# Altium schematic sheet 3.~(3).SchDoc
size 420 x 297 mm
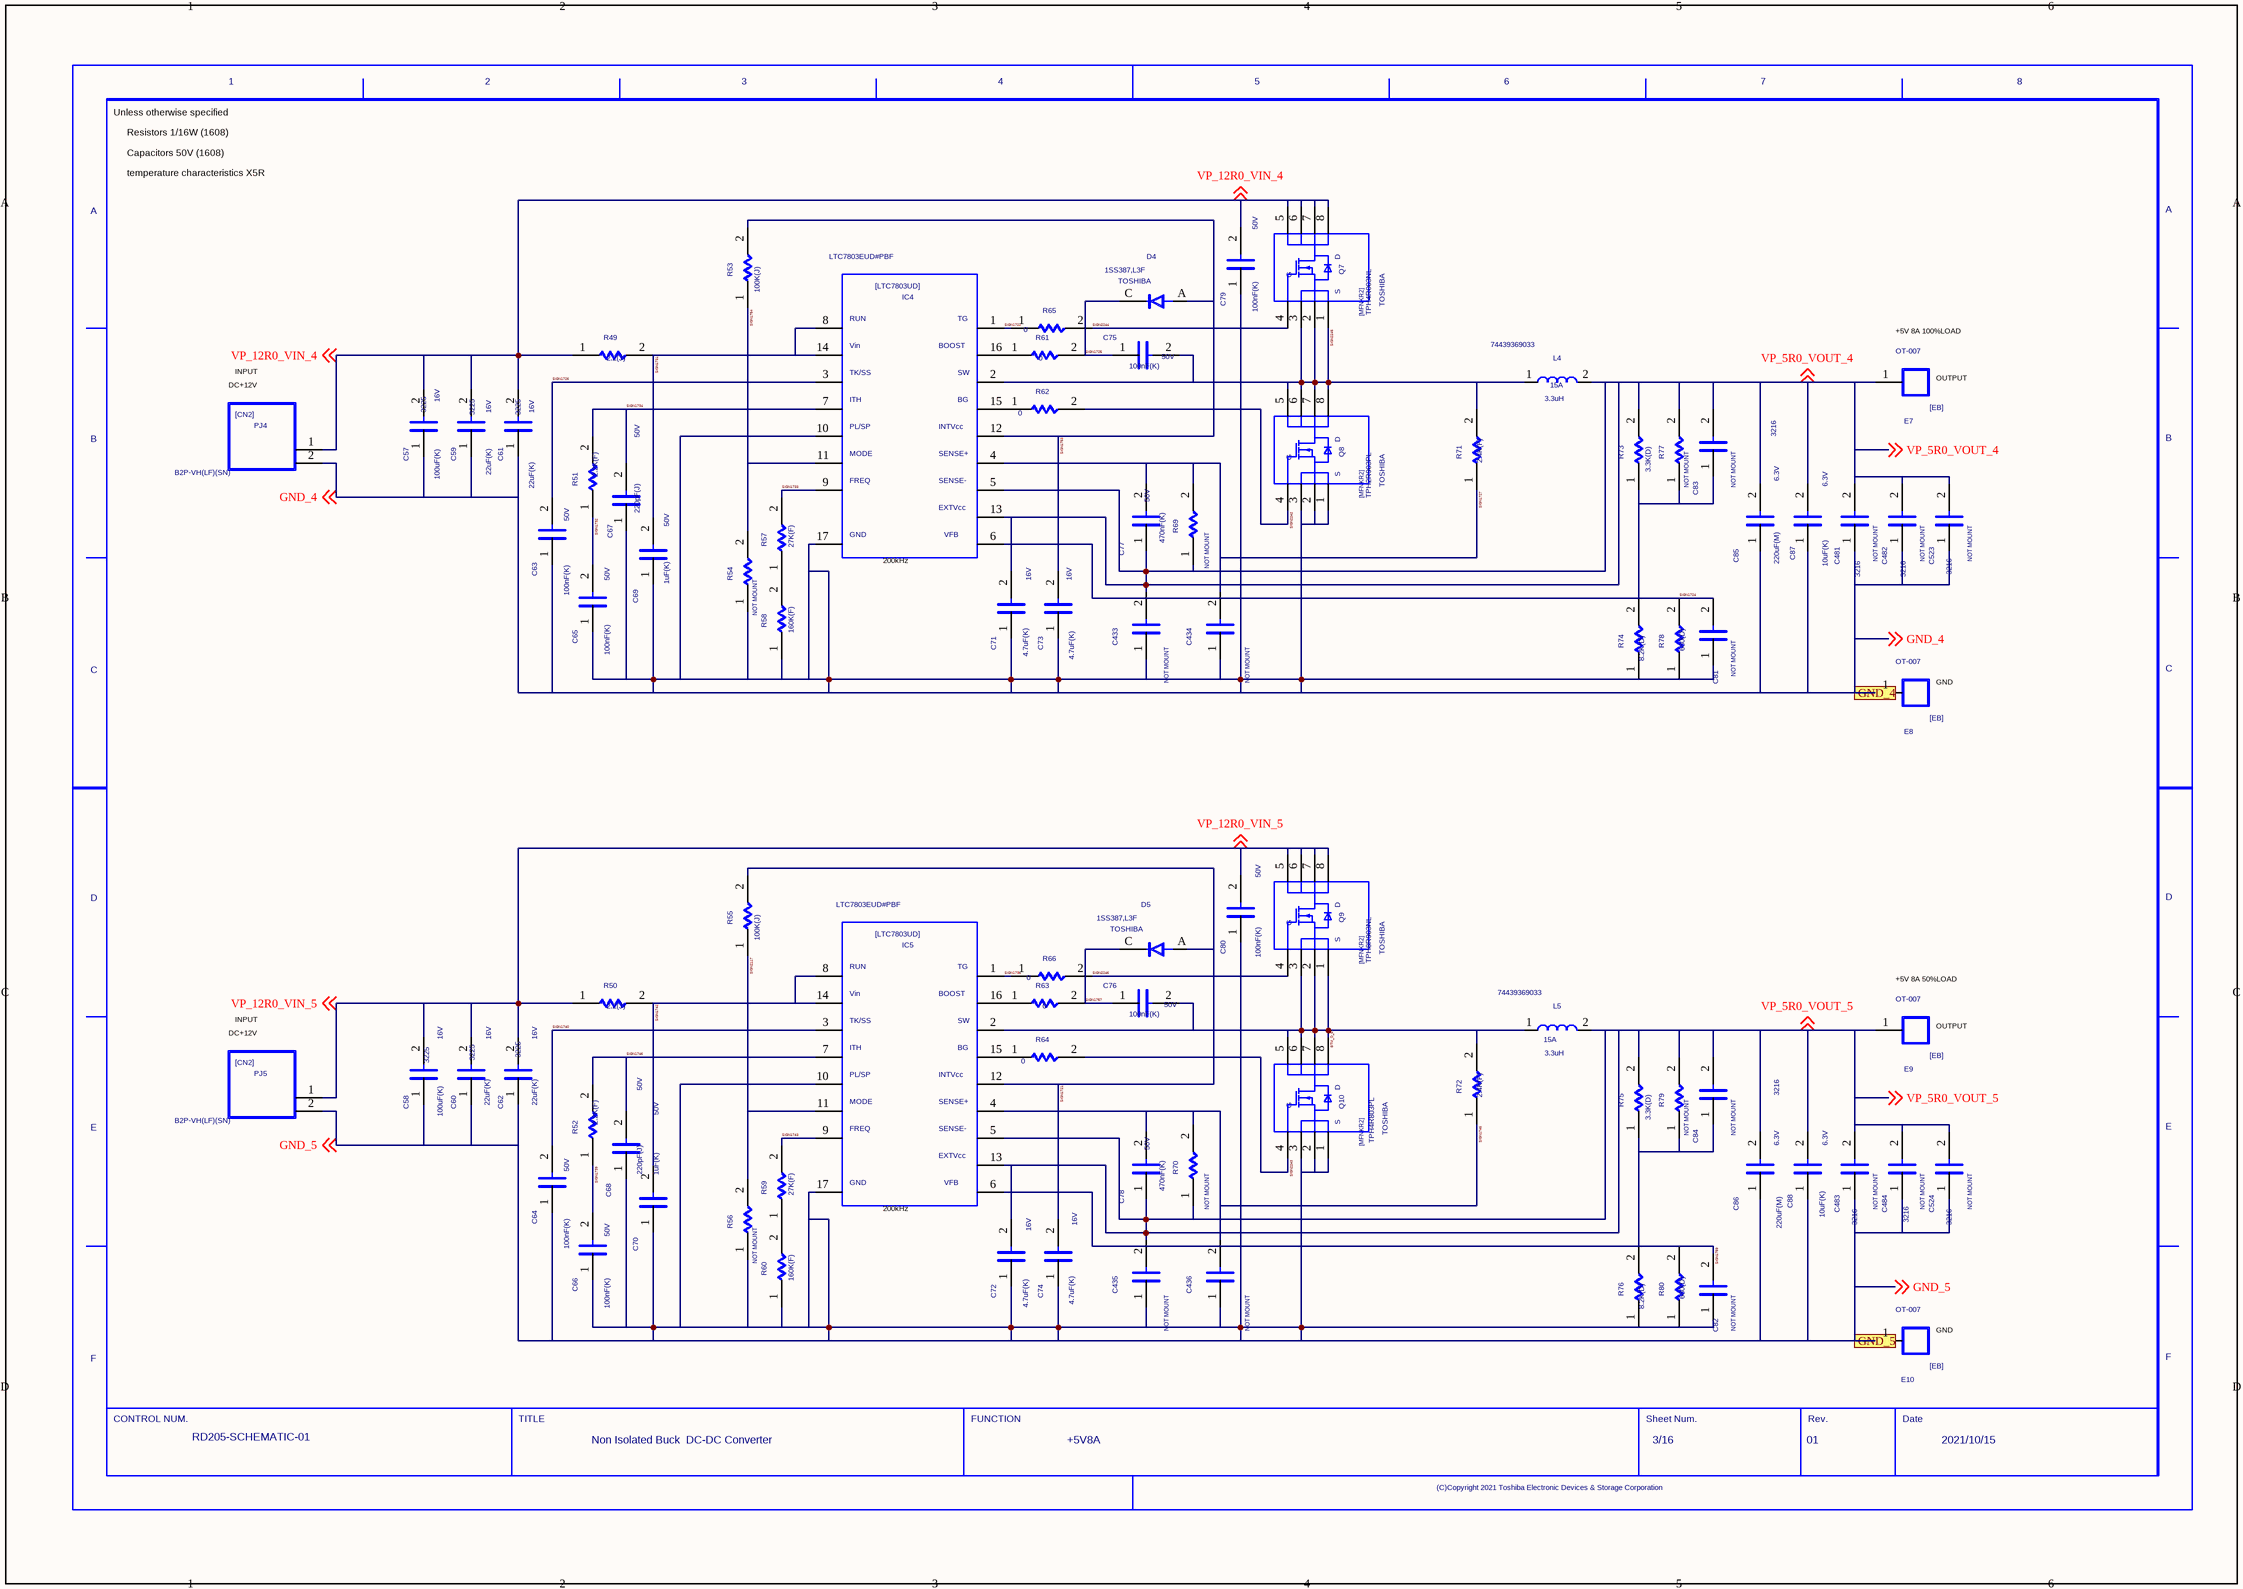
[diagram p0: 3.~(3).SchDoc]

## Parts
C57  SIZECODESMD: 3225  VAL2: 16V  VAL1: 100uF(K)  (hidden comment: C)
C58  SIZECODESMD: 3225  VAL2: 16V  VAL1: 100uF(K)  (hidden comment: C)
C59  SIZECODESMD: 3225  VAL2: 16V  VAL1: 22uF(K)  (hidden comment: C)
C60  SIZECODESMD: 3225  VAL2: 16V  VAL1: 22uF(K)  (hidden comment: C)
C61  SIZECODESMD: 3225  VAL2: 16V  VAL1: 22uF(K)  (hidden comment: C)
C62  SIZECODESMD: 3225  VAL2: 16V  VAL1: 22uF(K)  (hidden comment: C)
C63  VAL2: 50V  VAL1: 100nF(K)  (hidden comment: C)
C64  VAL2: 50V  VAL1: 100nF(K)  (hidden comment: C)
C65  VAL2: 50V  VAL1: 100nF(K)  (hidden comment: C)
C66  VAL2: 50V  VAL1: 100nF(K)  (hidden comment: C)
C67  VAL2: 50V  VAL1: 220pF(J)  (hidden comment: C)
C68  VAL2: 50V  VAL1: 220pF(J)  (hidden comment: C)
C69  VAL2: 50V  VAL1: 1uF(K)  (hidden comment: C)
C70  VAL2: 50V  VAL1: 1uF(K)  (hidden comment: C)
C71  VAL2: 16V  VAL1: 4.7uF(K)  (hidden comment: C)
C72  VAL2: 16V  VAL1: 4.7uF(K)  (hidden comment: C)
C73  VAL2: 16V  VAL1: 4.7uF(K)  (hidden comment: C)
C74  VAL2: 16V  VAL1: 4.7uF(K)  (hidden comment: C)
C75  VAL2: 50V  VAL1: 100nF(K)  (hidden comment: C)
C76  VAL2: 50V  VAL1: 100nF(K)  (hidden comment: C)
C77  VAL2: 50V  VAL1: 470nF(K)  (hidden comment: C)
C78  VAL2: 50V  VAL1: 470nF(K)  (hidden comment: C)
C79  VAL2: 50V  VAL1: 100nF(K)  (hidden comment: C)
C80  VAL2: 50V  VAL1: 100nF(K)  (hidden comment: C)
C81  NOTMOUNT: NOT MOUNT  (hidden comment: C)
C82  NOTMOUNT: NOT MOUNT  (hidden comment: C)
C83  NOTMOUNT: NOT MOUNT  (hidden comment: C)
C84  NOTMOUNT: NOT MOUNT  (hidden comment: C)
C85  SIZECODESMD: 3216  VAL2: 6.3V  VAL1: 220uF(M)  (hidden comment: C)
C86  SIZECODESMD: 3216  VAL2: 6.3V  VAL1: 220uF(M)  (hidden comment: C)
C87  VAL2: 6.3V  VAL1: 10uF(K)  (hidden comment: C)
C88  VAL2: 6.3V  VAL1: 10uF(K)  (hidden comment: C)
C433  NOTMOUNT: NOT MOUNT  (hidden comment: C)
C434  NOTMOUNT: NOT MOUNT  (hidden comment: C)
C435  NOTMOUNT: NOT MOUNT  (hidden comment: C)
C436  NOTMOUNT: NOT MOUNT  (hidden comment: C)
C481  NOTMOUNT: NOT MOUNT  SIZECODESMD: 3216  (hidden comment: C)
C482  NOTMOUNT: NOT MOUNT  SIZECODESMD: 3216  (hidden comment: C)
C483  NOTMOUNT: NOT MOUNT  SIZECODESMD: 3216  (hidden comment: C)
C484  NOTMOUNT: NOT MOUNT  SIZECODESMD: 3216  (hidden comment: C)
C523  NOTMOUNT: NOT MOUNT  SIZECODESMD: 3216  (hidden comment: C)
C524  NOTMOUNT: NOT MOUNT  SIZECODESMD: 3216  (hidden comment: C)
D4  USERCOMPTEXT3: TOSHIBA  VAL3: 1SS387,L3F  (hidden comment: D)
D5  USERCOMPTEXT3: TOSHIBA  VAL3: 1SS387,L3F  (hidden comment: D)
E7  VAL3: OT-007  (hidden comment: EB)
E8  VAL3: OT-007  (hidden comment: EB)
E9  VAL3: OT-007  (hidden comment: EB)
E10  VAL3: OT-007  (hidden comment: EB)
IC4  VAL3: LTC7803EUD#PBF  (hidden comment: LTC7803UD)
IC5  VAL3: LTC7803EUD#PBF  (hidden comment: LTC7803UD)
L4  VAL3: 74439369033  VAL2: 15A  VAL1: 3.3uH  (hidden comment: L)
L5  VAL3: 74439369033  VAL2: 15A  VAL1: 3.3uH  (hidden comment: L)
PJ4  VAL3: B2P-VH(LF)(SN)  (hidden comment: CN2)
PJ5  VAL3: B2P-VH(LF)(SN)  (hidden comment: CN2)
Q7  USERCOMPTEXT3: TOSHIBA  VAL3: TPH4R003NL  (hidden comment: MFNKR2)
Q8  USERCOMPTEXT3: TOSHIBA  VAL3: TPH2R903PL  (hidden comment: MFNKR2)
Q9  USERCOMPTEXT3: TOSHIBA  VAL3: TPH8R903NL  (hidden comment: MFNKR2)
Q10  USERCOMPTEXT3: TOSHIBA  VAL3: TPH4R803PL  (hidden comment: MFNKR2)
R49  VAL1: 2.2(J)  (hidden comment: R)
R50  VAL1: 2.2(J)  (hidden comment: R)
R51  VAL1: 2.2K(F)  (hidden comment: R)
R52  VAL1: 2.2K(F)  (hidden comment: R)
R53  VAL1: 100K(J)  (hidden comment: R)
R54  NOTMOUNT: NOT MOUNT  (hidden comment: R)
R55  VAL1: 100K(J)  (hidden comment: R)
R56  NOTMOUNT: NOT MOUNT  (hidden comment: R)
R57  VAL1: 27K(F)  (hidden comment: R)
R58  VAL1: 160K(F)  (hidden comment: R)
R59  VAL1: 27K(F)  (hidden comment: R)
R60  VAL1: 160K(F)  (hidden comment: R)
R61  VAL1: 0  (hidden comment: R)
R62  VAL1: 0  (hidden comment: R)
R63  VAL1: 0  (hidden comment: R)
R64  VAL1: 0  (hidden comment: R)
R65  VAL1: 0  (hidden comment: R)
R66  VAL1: 0  (hidden comment: R)
R69  NOTMOUNT: NOT MOUNT  (hidden comment: R)
R70  NOTMOUNT: NOT MOUNT  (hidden comment: R)
R71  VAL1: 2.4K(F)  (hidden comment: R)
R72  VAL1: 2.4K(F)  (hidden comment: R)
R73  VAL1: 3.3K(D)  (hidden comment: R)
R74  VAL1: 8.2K(D)  (hidden comment: R)
R75  VAL1: 3.3K(D)  (hidden comment: R)
R76  VAL1: 8.2K(D)  (hidden comment: R)
R77  NOTMOUNT: NOT MOUNT  (hidden comment: R)
R78  VAL1: 680(D)  (hidden comment: R)
R79  NOTMOUNT: NOT MOUNT  (hidden comment: R)
R80  VAL1: 680(D)  (hidden comment: R)
U?  DATE: 2021/10/15  SHEETNUMBER: 3/16  TITLE: Non Isolated Buck / DC-DC Converter  REVISION: 01  DRAWINGNUMBER: RD205-SCHEMATIC-01  FUNCTION: +5V8A  (hidden comment: WAKU_DEF100)

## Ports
GND_4, GND_5

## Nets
BTM_D_5: C76.2 IC5.2 L5.1 Q9.1 Q9.2 Q9.3 Q10.5 Q10.6 Q10.7 Q10.8 R72.2
GND_4: C57.1 C59.1 C61.1 C63.1 C65.1 C67.1 C69.1 C71.1 C73.1 C79.1 C81.1 C85.1 C87.1 C433.1 C434.1 C481.1 C482.1 C523.1 E8.1 IC4.10 IC4.17 PJ4.2 Q8.1 Q8.2 Q8.3 R54.1 R58.1 R74.1 R78.1 ; off-sheet GND_4, port GND_4
GND_5: C58.1 C60.1 C62.1 C64.1 C66.1 C68.1 C70.1 C72.1 C74.1 C80.1 C82.1 C86.1 C88.1 C435.1 C436.1 C483.1 C484.1 C524.1 E10.1 IC5.10 IC5.17 PJ5.2 Q10.1 Q10.2 Q10.3 R56.1 R60.1 R76.1 R80.1 ; off-sheet GND_5, port GND_5
SIGN1721: C74.2 D5.A IC5.12 R55.2
SIGN1722: IC4.1 R65.1
SIGN1724: C81.2 C83.1 IC4.6 R73.1 R74.2 R77.1 R78.2
SIGN1725: C75.1 D4.C R61.2
SIGN1726: C63.2 IC4.3
SIGN1727: C77.2 C434.2 IC4.4 R69.2 R71.1
SIGN1731: C69.2 IC4.8 IC4.14 R49.2
SIGN1732: C65.2 R51.1
SIGN1733: IC4.9 R57.2
SIGN1734: C67.2 IC4.7 R51.2
SIGN1736: IC5.1 R66.1
SIGN1739: C66.2 R52.1
SIGN1740: C64.2 IC5.3
SIGN1742: C70.2 IC5.8 IC5.14 R50.2
SIGN1743: IC5.9 R59.2
SIGN1745: C78.2 C436.2 IC5.4 R70.2 R72.1
SIGN1746: C68.2 IC5.7 R52.2
SIGN1753: C73.2 D4.A IC4.12 R53.2
SIGN1754: IC4.11 R53.1 R54.2
SIGN1757: C76.1 D5.C R63.2
SIGN1759: C82.2 C84.1 IC5.6 R75.1 R76.2 R79.1 R80.2
SIGN2117: IC5.11 R55.1 R56.2
SIGN2242: Q8.4 R62.2
SIGN2243: Q10.4 R64.2
SIGN2244: Q7.4 R65.2
SIGN2245: C75.2 IC4.2 L4.1 Q7.1 Q7.2 Q7.3 Q8.5 Q8.6 Q8.7 Q8.8 R71.2
SIGN2246: Q9.4 R66.2
VP_5R0_VOUT_4: C71.2 C77.1 C83.2 C85.2 C87.2 C433.2 C481.2 C482.2 C523.2 E7.1 IC4.5 IC4.13 L4.2 R69.1 R73.2 R77.2 ; off-sheet VP_5R0_VOUT_4
VP_5R0_VOUT_5: C72.2 C78.1 C84.2 C86.2 C88.2 C435.2 C483.2 C484.2 C524.2 E9.1 IC5.5 IC5.13 L5.2 R70.1 R75.2 R79.2 ; off-sheet VP_5R0_VOUT_5
VP_12R0_VIN_4: C57.2 C59.2 C61.2 C79.2 PJ4.1 Q7.5 Q7.6 Q7.7 Q7.8 R49.1 ; off-sheet VP_12R0_VIN_4
VP_12R0_VIN_5: C58.2 C60.2 C62.2 C80.2 PJ5.1 Q9.5 Q9.6 Q9.7 Q9.8 R50.1 ; off-sheet VP_12R0_VIN_5
NetIC4_15: IC4.15 R62.1
NetIC4_16: IC4.16 R61.1
NetIC5_15: IC5.15 R64.1
NetIC5_16: IC5.16 R63.1
NetR57_1: R57.1 R58.2
NetR59_1: R59.1 R60.2

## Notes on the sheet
- Unless otherwise specified
- Resistors 1/16W (1608)
- Capacitors 50V (1608)
- temperature characteristics X5R
- DC+12V
- INPUT
- (near E7) +5V 8A 100%LOAD
- (near E7) OUTPUT
- (near IC4) 200kHz
- (near E8) GND
- (near E9) +5V 8A 50%LOAD
- (near E9) OUTPUT
- (near IC5) 200kHz
- (near E10) GND

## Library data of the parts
C57 C58 = C_Dup1: SQ_PART_MODEL: CON_100n; FNPARTSNAMEG: CHIP CERAMIC CAPACITOR (3225); USEINPARTSLIST: YES; OriginalSymbolOrigin: (2540,7620); MFSOLDERINGPROP: .; TEMPCHARACTERI2: B; MFFORMINGDIVP: KC; OUMECLASSIFICATION: セラミックコンデンサ; MFMOUNTSYMBOLP: 90; CDMASTERCADCELG: DC903A; PCODE: P03276001115; FNCLASSCODEG: P03-03; MAXGCOUNT: 1; RATEDVOLTAGE: 250; COMPONENTNAME: G36030160049; OUMEMAKER: KYC 京セラ; MFPACKAGEMETHOP: S; NOMINALCAPACITA: 100n; OUMEMAKERKATAMEI: CF32W5R104K250AT; CAPACITANCETOLE: K
C59-C62 = C_Dup1: SQ_PART_MODEL: CON_22u; FNPARTSNAMEG: CHIP CERAMIC CAPACITOR (3225); USEINPARTSLIST: YES; OriginalSymbolOrigin: (2540,7620); MFSOLDERINGPROP: .; TEMPCHARACTERI2: B; MFFORMINGDIVP: KC; OUMECLASSIFICATION: セラミックコンデンサ; MFMOUNTSYMBOLP: 80; CDMASTERCADCELG: DC903A; PCODE: P03043035626; FNCLASSCODEG: P03-03; MAXGCOUNT: 1; RATEDVOLTAGE: 6.3; COMPONENTNAME: G36030119054; OUMEMAKER: TYD 太陽誘電; MFPACKAGEMETHOP: S; NOMINALCAPACITA: 22u; OUMEMAKERKATAMEI: JMK325BJ226KM-T; CAPACITANCETOLE: K
C63-C66 C75 C76 C79 C80 = C_Dup1: SQ_PART_MODEL: CON_100n; FNPARTSNAMEG: CHIP CERAMIC CAPACITOR (1608); USEINPARTSLIST: YES; OriginalSymbolOrigin: (2540,7620); MFSOLDERINGPROP: .; TEMPCHARACTERI2: B; MFFORMINGDIVP: KC; OUMECLASSIFICATION: セラミックコンデンサ; SIZECODESMD: 1608; MFMOUNTSYMBOLP: 80; CDMASTERCADCELG: C8100E; PCODE: P03B000000E4; FNCLASSCODEG: P03-03; MAXGCOUNT: 1; RATEDVOLTAGE: 16; COMPONENTNAME: GDM030000598; OUMEMAKER: MRT 村田製作所; MFPACKAGEMETHOP: S; NOMINALCAPACITA: 100n; OUMEMAKERKATAMEI: GRM188B11C104KA01C; CAPACITANCETOLE: K
C67 C68 = C_Dup1: SQ_PART_MODEL: CON_220p; FNPARTSNAMEG: CHIP CERAMIC CAPACITOR (1608); USEINPARTSLIST: YES; OriginalSymbolOrigin: (2540,7620); CDMASTERCADCELG: C8100E; MFSOLDERINGPROP: .; TEMPCHARACTERI2: CH; MFFORMINGDIVP: KC; OUMECLASSIFICATION: セラミックコンデンサ; SIZECODESMD: 1608; MFMOUNTSYMBOLP: 80; PCODE: P03039269127; FNCLASSCODEG: P03-03; MAXGCOUNT: 1; RATEDVOLTAGE: 50; COMPONENTNAME: G36030011488; OUMEMAKER: KYC 京セラ; MFPACKAGEMETHOP: S; NOMINALCAPACITA: 220p; OUMEMAKERKATAMEI: CM105CH221J50AT; CAPACITANCETOLE: J
C69 C70 = C_Dup1: SQ_PART_MODEL: CON_1u; FNPARTSNAMEG: CHIP CERAMIC CAPACITOR (1608); USEINPARTSLIST: YES; OriginalSymbolOrigin: (2540,7620); MFSOLDERINGPROP: .; TEMPCHARACTERI2: B; MFFORMINGDIVP: KC; OUMECLASSIFICATION: セラミックコンデンサ; SIZECODESMD: 1608; MFMOUNTSYMBOLP: 80; CDMASTERCADCELG: C8100E; PCODE: P03039ACE122; FNCLASSCODEG: P03-03; MAXGCOUNT: 1; RATEDVOLTAGE: 6.3; COMPONENTNAME: G36030104159; OUMEMAKER: KYC 京セラ; MFPACKAGEMETHOP: S; NOMINALCAPACITA: 1u; OUMEMAKERKATAMEI: CM105B105K06ATN; CAPACITANCETOLE: K
C71 C72 = C_Dup1: SQ_PART_MODEL: CON_4.7u; FNPARTSNAMEG: CHIP CERAMIC CAPACITOR (1608); USEINPARTSLIST: YES; OriginalSymbolOrigin: (2540,7620); PCODE: P03B000000MS; MFSOLDERINGPROP: .; TEMPCHARACTERI2: B; MFFORMINGDIVP: KC; OUMECLASSIFICATION: セラミックコンデンサ; SIZECODESMD: 1608; MFMOUNTSYMBOLP: 80; CDMASTERCADCELG: C8100E; FNCLASSCODEG: P03-03; MAXGCOUNT: 1; RATEDVOLTAGE: 4; COMPONENTNAME: GDM030000053; OUMEMAKER: KYC 京セラ; MFPACKAGEMETHOP: S; NOMINALCAPACITA: 4.7u; OUMEMAKERKATAMEI: CM105B475M04AT; CAPACITANCETOLE: M
C73 C74 = C_Dup1: SQ_PART_MODEL: CON_4.7u; FNPARTSNAMEG: CHIP CERAMIC CAPACITOR (1608); USEINPARTSLIST: YES; OriginalSymbolOrigin: (2540,7620); MFSOLDERINGPROP: .; TEMPCHARACTERI2: B; MFFORMINGDIVP: KC; OUMECLASSIFICATION: セラミックコンデンサ; SIZECODESMD: 1608; MFMOUNTSYMBOLP: 80; CDMASTERCADCELG: C8100E; PCODE: P03B000000MS; FNCLASSCODEG: P03-03; MAXGCOUNT: 1; RATEDVOLTAGE: 4; COMPONENTNAME: GDM030000053; OUMEMAKER: KYC 京セラ; MFPACKAGEMETHOP: S; NOMINALCAPACITA: 4.7u; OUMEMAKERKATAMEI: CM105B475M04AT; CAPACITANCETOLE: M
C77 C78 = C_Dup1: SQ_PART_MODEL: CON_470n; FNPARTSNAMEG: CHIP CERAMIC CAPACITOR (1608); USEINPARTSLIST: YES; OriginalSymbolOrigin: (2540,7620); MFSOLDERINGPROP: .; TEMPCHARACTERI2: B; MFFORMINGDIVP: KC; OUMECLASSIFICATION: セラミックコンデンサ; SIZECODESMD: 1608; MFMOUNTSYMBOLP: 80; CDMASTERCADCELG: C8100E; PCODE: P03039ABG127; FNCLASSCODEG: P03-03; MAXGCOUNT: 1; RATEDVOLTAGE: 10; COMPONENTNAME: GDM030001129; OUMEMAKER: KYC 京セラ; MFPACKAGEMETHOP: S; NOMINALCAPACITA: 470n; OUMEMAKERKATAMEI: CM105B474K10AT; CAPACITANCETOLE: K
C81-C84 = C_Dup1: SQ_PART_MODEL: CON_100p; FNPARTSNAMEG: CHIP CERAMIC CAPACITOR (1608); USEINPARTSLIST: YES; OriginalSymbolOrigin: (2540,7620); TOLERANCE: J; ASIMVALUE: 100P; MFSOLDERINGPROP: .; TEMPCHARACTERI2: CH; MFFORMINGDIVP: KC; OUMECLASSIFICATION: セラミックコンデンサ; SIZECODESMD: 1608; MFMOUNTSYMBOLP: 80; CDMASTERCADCELG: C8100E; PCODE: P03039177125; FNCLASSCODEG: P03-03; MAXGCOUNT: 1; RATEDVOLTAGE: 50; COMPONENTNAME: G36030011365; OUMEMAKER: KYC 京セラ; MFPACKAGEMETHOP: S; OUMEMAKERKATAMEI: CM105CH101J50AT; VAL2: 50V; VAL1: 100pF(J)
C85 C86 = C_Dup1: SQ_PART_MODEL: CON_22u; FNPARTSNAMEG: CHIP CERAMIC CAPACITOR (3216); USEINPARTSLIST: YES; OriginalSymbolOrigin: (2540,7620); MFSOLDERINGPROP: .; TEMPCHARACTERI2: B; MFFORMINGDIVP: KC; OUMECLASSIFICATION: セラミックコンデンサ; MFMOUNTSYMBOLP: 80; CDMASTERCADCELG: DC901A; PCODE: P03B0000004V; FNCLASSCODEG: P03-03; MAXGCOUNT: 1; RATEDVOLTAGE: 6.3; COMPONENTNAME: GDM030000020; OUMEMAKER: KYC 京セラ; MFPACKAGEMETHOP: S; NOMINALCAPACITA: 22u; OUMEMAKERKATAMEI: CM316B226M06AT; CAPACITANCETOLE: M
C87 C88 = C_Dup1: SQ_PART_MODEL: CON_1u; FNPARTSNAMEG: CHIP CERAMIC CAPACITOR (1608); PARTCOMMENT: 代表セル<KC0008> がフットプリントに登録されていません。; USEINPARTSLIST: YES; OriginalSymbolOrigin: (2540,7620); MFSOLDERINGPROP: .; TEMPCHARACTERI2: B; MFFORMINGDIVP: KC; OUMECLASSIFICATION: セラミックコンデンサ; SIZECODESMD: 1608; MFMOUNTSYMBOLP: 80; CDMASTERCADCELG: KC0008; PCODE: P03B000000ZQ; FNCLASSCODEG: P03-03; MAXGCOUNT: 1; RATEDVOLTAGE: 6.3; COMPONENTNAME: GDM030000202; OUMEMAKER: MRT 村田製作所; MFPACKAGEMETHOP: S; NOMINALCAPACITA: 1u; OUMEMAKERKATAMEI: GRM185B10J105KE21D; CAPACITANCETOLE: K
C433-C436 = C_Dup1: SQ_PART_MODEL: CON_220n; FNPARTSNAMEG: CHIP CERAMIC CAPACITOR (1608); PARTCOMMENT: 代表セル<KC0008> がフットプリントに登録されていません。; USEINPARTSLIST: YES; OriginalSymbolOrigin: (2540,7620); MFSOLDERINGPROP: .; TEMPCHARACTERI2: B; MFFORMINGDIVP: KC; OUMECLASSIFICATION: セラミックコンデンサ; SIZECODESMD: 1608; MFMOUNTSYMBOLP: 80; CDMASTERCADCELG: KC0008; PCODE: P03B000001L3; FNCLASSCODEG: P03-03; MAXGCOUNT: 1; RATEDVOLTAGE: 16; COMPONENTNAME: GDM030001129; OUMEMAKER: MRT 村田製作所; MFPACKAGEMETHOP: S; NOMINALCAPACITA: 220n; OUMEMAKERKATAMEI: GRM188B11C224KA01D; VAL2: 16V; VAL1: 220nF(K); CAPACITANCETOLE: K
C481-C484 C523 C524 = C_Dup1: SQ_PART_MODEL: CON_22u; FNPARTSNAMEG: CHIP CERAMIC CAPACITOR (3216); USEINPARTSLIST: YES; OriginalSymbolOrigin: (2540,7620); MFSOLDERINGPROP: .; TEMPCHARACTERI2: B; MFFORMINGDIVP: KC; OUMECLASSIFICATION: セラミックコンデンサ; MFMOUNTSYMBOLP: 80; CDMASTERCADCELG: DC901A; PCODE: P03B0000004V; FNCLASSCODEG: P03-03; MAXGCOUNT: 1; RATEDVOLTAGE: 6.3; COMPONENTNAME: GDM030000020; OUMEMAKER: KYC 京セラ; MFPACKAGEMETHOP: S; NOMINALCAPACITA: 22u; OUMEMAKERKATAMEI: CM316B226M06AT; VAL2: 6.3V; VAL1: 22uF(M); CAPACITANCETOLE: M
D4 D5 = D_Dup1: FNPARTSNAMEG: DIODE; USEINPARTSLIST: YES; PARTNAME: GDM420000143; SAVEAREA0: -565,-171,12979,8058; SAVECOUNT: 1; OriginalSymbolOrigin: (2540,5080); FORWARDVOLTAGEM: 0; MAXREVERSEVOLTA: 80; COMPONENTNAME: GDM420000143_package; MFSOLDERINGPROP: .; OUMEMAKER: TSB 東芝（ＹＰＳＳ）; QUADMODEL: dummymodel; MFPACKAGEMETHOP: S; MFFORMINGDIVP: MM; MOUNTINGFORMSMD: SMD; OUMECLASSIFICATION: 小信号ダイオード; OUMEMAKERKATAMEI: 1SS387(TPH3,F); CDMASTERCADCELG: D8101D; PCODE: P42B0000008E; FNCLASSCODEG: P42-01
E7-E10 = EB_Dup1: FNPARTSNAMEG: TERMINAL; USEINPARTSLIST: YES; PARTNAME: 5P9L1232P001; OUMEPARTTYPE: TB; OriginalSymbolOrigin: (2540,12700); COMPONENTNAME: 5P9L1232P001_package; MAXGCOUNT: 1; MFSOLDERINGPROP: .; OUMEMAKER: オサダ; QUADMODEL: dummymodel; MFPACKAGEMETHOP: I; MFFORMINGDIVP: OD; OUMECLASSIFICATION: 端子台、端子板; CDMASTERCADCELG: DE0009; KIND: PBS; PCODE: P29045001117; TERMINALSTYLE: SC; FNCLASSCODEG: P29-01
IC4 IC5 = LTC7803UD: USEINPARTSLIST: YES; SAVECOUNT: 29; SAVEAREA0: -53177,0,89020,58420; TIME: 16:14:14; UPDATEUSER: q91866sr; UPDATETIME: 13:15:36; OriginalSymbolOrigin: (5080,55880); MAXGCOUNT: 1; COMPONENTNAME: LTC7803UD_LTC7803UD; OUMEMAKER: ANALOG DEVICES
L4 L5 = L_Dup1: USEINPARTSLIST: YES; OriginalSymbolOrigin: (2540,5080); MAXGCOUNT: 1; COMPONENTNAME: L_L; OUMEMAKER: WURTH
PJ4 PJ5 = CN2_Dup1: FNPARTSNAMEG: 3.96PITCH NYLON CONNECTOR; USEINPARTSLIST: YES; PARTNAME: G36220114012; OUMEPARTTYPE: CN; OriginalSymbolOrigin: (2540,15240); MAXGCOUNT: 1; RATEDCURRENT: 7; COMPONENTNAME: G36220114012_package; MFSOLDERINGPROP: .; OUMEMAKER: JST 日本圧着端子製造; NUMBEROFCONTACT: 2; QUADMODEL: dummymodel; MFPACKAGEMETHOP: I; MFFORMINGDIVP: CU; CONTACTPITCH: 3.96m; OUMEMAKERKATAMEI: B2P-VH; CDMASTERCADCELG: DPJ514; PCODE: P22346001114; TERMINALSTYLE: PW; FNCLASSCODEG: P22-10
Q7-Q10 = MFNKR2: USEINPARTSLIST: YES; PARTNAME: TPH6R003NL; SAVEAREA0: -9199,-39,32138,22820; TIME: 18:57:44; UPDATEUSER: q91866sr; UPDATETIME: 12:36:02; SAVECOUNT: 10; OriginalSymbolOrigin: (5080,20320); MAXGCOUNT: 1; COMPONENTNAME: MFNKR2_MFNKR2
R49 R50 = R_Dup1: SQ_PART_MODEL: RES_2.2; FNPARTSNAMEG: CHIP RESISTOR (1608); USEINPARTSLIST: YES; OriginalSymbolOrigin: (5080,5080); TOLERANCE: J; ASIMVALUE: 2.2; MAXGCOUNT: 1; COMPONENTNAME: G36010011507; MFSOLDERINGPROP: .; OUMEMAKER: NAE 松下電子部品; MFPACKAGEMETHOP: S; MFFORMINGDIVP: KC; MOUNTINGFORMSMD: SMD; OUMECLASSIFICATION: 表面実装用固定抵抗器; MFMOUNTSYMBOLP: 80; POWERRATING: 63m; OUMEMAKERKATAMEI: ERJ3GEYJ2R2V; NUMBEROFELEMENT: 0; VAL2: 62.5mW; CDMASTERCADCELG: DR802R; PCODE: P01042157622; FNCLASSCODEG: P01-08
R51 R52 = R_Dup1: SQ_PART_MODEL: RES_2.2K; FNPARTSNAMEG: CHIP RESISTOR (1608); USEINPARTSLIST: YES; OriginalSymbolOrigin: (5080,5080); MAXGCOUNT: 1; COMPONENTNAME: G36010104339; MFSOLDERINGPROP: .; OUMEMAKER: KOA ＫＯＡ; MFPACKAGEMETHOP: S; MFFORMINGDIVP: KC; MOUNTINGFORMSMD: SMD; OUMECLASSIFICATION: 表面実装用固定抵抗器; RESISTANCETOLER: F; MFMOUNTSYMBOLP: 80; POWERRATING: 63m; OUMEMAKERKATAMEI: RK73H1JTD2201F; NOMINALRESISTAN: 2.2K; NUMBEROFELEMENT: 0; VAL2: 62.5mW; CDMASTERCADCELG: DR802R; PCODE: P01042159428; FNCLASSCODEG: P01-08
R53 R55 = R_Dup1: SQ_PART_MODEL: RES_100K; FNPARTSNAMEG: CHIP RESISTOR (1608); USEINPARTSLIST: YES; OriginalSymbolOrigin: (5080,5080); TOLERANCE: J; ASIMVALUE: 100K; MFSOLDERINGPROP: .; MFPACKAGEMETHOP: S; MFFORMINGDIVP: KC; MOUNTINGFORMSMD: SMD; MFMOUNTSYMBOLP: 80; NUMBEROFELEMENT: 0; PCODE: P01042047220; MAXGCOUNT: 1; COMPONENTNAME: G36010011057; OUMEMAKER: HDK 北陸電気工業; OUMECLASSIFICATION: 表面実装用固定抵抗器; POWERRATING: 63m; OUMEMAKERKATAMEI: CR1/16 104JV; VAL2: 62.5mW; CDMASTERCADCELG: DR802R; FNCLASSCODEG: P01-08
R54 R56 = R_Dup1: SQ_PART_MODEL: RES_10; FNPARTSNAMEG: CHIP RESISTOR (1608); USEINPARTSLIST: YES; OriginalSymbolOrigin: (5080,5080); TOLERANCE: F; ASIMVALUE: 10; MFSOLDERINGPROP: .; MFPACKAGEMETHOP: S; MFFORMINGDIVP: KC; MOUNTINGFORMSMD: SMD; MFMOUNTSYMBOLP: 80; NUMBEROFELEMENT: 0; PCODE: P01042036620; MAXGCOUNT: 1; COMPONENTNAME: G36010104063; OUMEMAKER: NAE 松下電子部品; OUMECLASSIFICATION: 表面実装用固定抵抗器; POWERRATING: 63m; OUMEMAKERKATAMEI: ERJ3GEYF100V; VAL2: 62.5mW; VAL1: 10(F); CDMASTERCADCELG: DR802R; FNCLASSCODEG: P01-08
R57 R59 = R_Dup1: SQ_PART_MODEL: RES_27K; FNPARTSNAMEG: CHIP RESISTOR (1608); USEINPARTSLIST: YES; OriginalSymbolOrigin: (5080,5080); MAXGCOUNT: 1; TOLERANCE: F; COMPONENTNAME: G36010027195; MFSOLDERINGPROP: .; OUMEMAKER: NAE 松下電子部品; MFPACKAGEMETHOP: S; MFFORMINGDIVP: KC; MOUNTINGFORMSMD: SMD; OUMECLASSIFICATION: 表面実装用固定抵抗器; ASIMVALUE: 27K; MFMOUNTSYMBOLP: 80; POWERRATING: 63m; OUMEMAKERKATAMEI: ERJ3GEYF273V; NUMBEROFELEMENT: 0; VAL2: 62.5mW; CDMASTERCADCELG: DR802R; PCODE: P01042508622; FNCLASSCODEG: P01-08
R58 R60 = R_Dup1: SQ_PART_MODEL: RES_160K; FNPARTSNAMEG: CHIP RESISTOR (1608); USEINPARTSLIST: YES; OriginalSymbolOrigin: (5080,5080); MAXGCOUNT: 1; COMPONENTNAME: G51011061108; MFSOLDERINGPROP: .; OUMEMAKER: HDK 北陸電気工業; MFPACKAGEMETHOP: S; MFFORMINGDIVP: KC; MOUNTINGFORMSMD: SMD; OUMECLASSIFICATION: 表面実装用固定抵抗器; RESISTANCETOLER: F; MFMOUNTSYMBOLP: 80; POWERRATING: 63m; OUMEMAKERKATAMEI: CR1/16 164FV; NOMINALRESISTAN: 160K; NUMBEROFELEMENT: 0; VAL2: 62.5mW; CDMASTERCADCELG: DR802R; PCODE: P01042125225; FNCLASSCODEG: P01-08
R61 R63 = R_Dup1: SQ_PART_MODEL: RES_10; FNPARTSNAMEG: CHIP RESISTOR (1608); USEINPARTSLIST: YES; OriginalSymbolOrigin: (5080,5080); TOLERANCE: F; ASIMVALUE: 10; MFSOLDERINGPROP: .; MFPACKAGEMETHOP: S; MFFORMINGDIVP: KC; MOUNTINGFORMSMD: SMD; MFMOUNTSYMBOLP: 80; PCODE: P01042036620; MAXGCOUNT: 1; COMPONENTNAME: G36010104063; OUMEMAKER: NAE 松下電子部品; OUMECLASSIFICATION: 表面実装用固定抵抗器; POWERRATING: 63m; OUMEMAKERKATAMEI: ERJ3GEYF100V; VAL2: 62.5mW; CDMASTERCADCELG: DR802R; FNCLASSCODEG: P01-08
R62 R64-R66 = R_Dup1: SQ_PART_MODEL: RES_10; FNPARTSNAMEG: CHIP RESISTOR (2012); USEINPARTSLIST: YES; OriginalSymbolOrigin: (5080,5080); MAXGCOUNT: 1; TOLERANCE: F; COMPONENTNAME: 5P9L1083P100; MFSOLDERINGPROP: .; OUMEMAKER: 北陸電気工業; MFPACKAGEMETHOP: S; MFFORMINGDIVP: KC; MOUNTINGFORMSMD: SMD; OUMECLASSIFICATION: 表面実装用固定抵抗器; ASIMVALUE: 10; MFMOUNTSYMBOLP: 90; POWERRATING: 100m; OUMEMAKERKATAMEI: CR1/10 100FV Pb(F); VAL2: 125mW; CDMASTERCADCELG: DR910A; PCODE: P01043091222; FNCLASSCODEG: P01-08
R69 R70 = R_Dup1: SQ_PART_MODEL: RES_47K; FNPARTSNAMEG: CHIP RESISTOR (1608); USEINPARTSLIST: YES; OriginalSymbolOrigin: (5080,5080); TOLERANCE: F; ASIMVALUE: 47K; MAXGCOUNT: 1; COMPONENTNAME: G36010027102; MFSOLDERINGPROP: .; OUMEMAKER: KOA ＫＯＡ; MFPACKAGEMETHOP: S; MFFORMINGDIVP: KC; MOUNTINGFORMSMD: SMD; OUMECLASSIFICATION: 表面実装用固定抵抗器; MFMOUNTSYMBOLP: 80; POWERRATING: 63m; OUMEMAKERKATAMEI: RK73H1JTD4702F; NUMBEROFELEMENT: 0; VAL2: 62.5mW; VAL1: 47K(F); CDMASTERCADCELG: DR802R; PCODE: P01042373428; FNCLASSCODEG: P01-08
R71 R72 = R_Dup1: SQ_PART_MODEL: RES_2.4K; FNPARTSNAMEG: CHIP RESISTOR (1608); USEINPARTSLIST: YES; OriginalSymbolOrigin: (5080,5080); TOLERANCE: F; ASIMVALUE: 2.4K; PCODE: P01042166327; MAXGCOUNT: 1; COMPONENTNAME: K0100562; MFSOLDERINGPROP: .; OUMEMAKER: KAM 釜屋電機; MFPACKAGEMETHOP: S; MFFORMINGDIVP: KC; MOUNTINGFORMSMD: SMD; OUMECLASSIFICATION: 表面実装用固定抵抗器; MFMOUNTSYMBOLP: 80; POWERRATING: 63m; OUMEMAKERKATAMEI: RMC1/16-242FTP; NUMBEROFELEMENT: 0; VAL2: 62.5mW; CDMASTERCADCELG: DR802R; FNCLASSCODEG: P01-08
R73 R75 = R_Dup1: SQ_PART_MODEL: RES_3.3K; FNPARTSNAMEG: CHIP RESISTOR (1608); USEINPARTSLIST: YES; OriginalSymbolOrigin: (5080,5080); MAXGCOUNT: 1; COMPONENTNAME: G36010014485; MFSOLDERINGPROP: .; OUMEMAKER: SSM 進工業; MFPACKAGEMETHOP: S; MFFORMINGDIVP: KC; MOUNTINGFORMSMD: SMD; OUMECLASSIFICATION: 表面実装用固定抵抗器; RESISTANCETOLER: D; MFMOUNTSYMBOLP: 80; POWERRATING: 63m; OUMEMAKERKATAMEI: RR0816P-332-D; NOMINALRESISTAN: 3.3K; NUMBEROFELEMENT: 0; VAL2: 62.5mW; CDMASTERCADCELG: DR802R; PCODE: P01042249822; FNCLASSCODEG: P01-08
R74 R76 = R_Dup1: ICX_PART_MODEL: RES_8.2K; FNPARTSNAMEG: CHIP RESISTOR (1608); OriginalSymbolOrigin: (5080,5080); FNCLASSCODEG: P01-08; PCODE: P01117051114; CDMASTERCADCELG: DR802R; USEWITHSCHEMA: YES; VAL2: 62.5mW; NUMBEROFELEMENT: 0; NOMINALRESISTAN: 8.2K; OUMEMAKERKATAMEI: RK73G1JTD822D; POWERRATING: 63m; MFMOUNTSYMBOLP: 80; RESISTANCETOLER: D; FUNCTION: G36010129479; OUMECLASSIFICATION: 表面実装用固定抵抗器; MOUNTINGFORMSMD: SMD; MFFORMINGDIVP: KC; MFPACKAGEMETHOP: S; OUMEMAKER: KOA ＫＯＡ; MFSOLDERINGPROP: .; MAXGCOUNT: 1
R77 R79 = R_Dup1: SQ_PART_MODEL: RES_3.3K; FNPARTSNAMEG: CHIP RESISTOR (1608); USEINPARTSLIST: YES; OriginalSymbolOrigin: (5080,5080); TOLERANCE: F; ASIMVALUE: 3.3K; MAXGCOUNT: 1; COMPONENTNAME: G36010027027; MFSOLDERINGPROP: .; OUMEMAKER: ROH ロー・; MFPACKAGEMETHOP: S; MFFORMINGDIVP: KC; MOUNTINGFORMSMD: SMD; OUMECLASSIFICATION: 表面実装用固定抵抗器; MFMOUNTSYMBOLP: 80; POWERRATING: 63m; OUMEMAKERKATAMEI: MCR03EZPFX3301; NUMBEROFELEMENT: 0; VAL2: 62.5mW; VAL1: 3.3K(F); CDMASTERCADCELG: DR802R; PCODE: P01042250729; FNCLASSCODEG: P01-08
R78 R80 = R_Dup1: ICX_PART_MODEL: RES_680; FNPARTSNAMEG: CHIP RESISTOR (1608); OriginalSymbolOrigin: (5080,5080); FNCLASSCODEG: P01-08; PCODE: P01117025115; CDMASTERCADCELG: DR802R; USEWITHSCHEMA: YES; VAL2: 62.5mW; NUMBEROFELEMENT: 0; NOMINALRESISTAN: 680; OUMEMAKERKATAMEI: RK73G1JTD681D; POWERRATING: 63m; MFMOUNTSYMBOLP: 80; RESISTANCETOLER: D; FUNCTION: G36010129219; OUMECLASSIFICATION: 表面実装用固定抵抗器; MOUNTINGFORMSMD: SMD; MFFORMINGDIVP: KC; MFPACKAGEMETHOP: S; OUMEMAKER: KOA ＫＯＡ; MFSOLDERINGPROP: .; MAXGCOUNT: 1
U? = WAKU_DEF100: PLOTTIME: HH:MM; SAVEAREA0: 330961,54,387907,31546; TIME: 19:23:07; UPDATEUSER: t5459927; UPDATETIME: 15:33:39; SAVECOUNT: 6; OriginalSymbolOrigin: (10160,284480); DESIGNED: ***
